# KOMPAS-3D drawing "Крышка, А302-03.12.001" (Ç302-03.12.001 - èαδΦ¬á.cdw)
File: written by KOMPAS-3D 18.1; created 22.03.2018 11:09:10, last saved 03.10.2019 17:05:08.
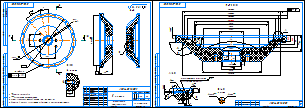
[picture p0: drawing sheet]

Sheets 1-2: A3, landscape

Document properties: Автор: Милов; Организация: Милов; Полное имя файла: D:\Мембранные насосы\Мембранный электропривод\А302-00.00.000 - ASTRA-302 (МЭ200)\Чертежи Полипропилен\А302-03.12.001 - Крышка.cdw; Масса: 2.71786; Параметр неуказанной шероховатости: Ra 3,2; Форматы листов документа: 2xA3

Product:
- Part/product: Крышка  | designation А302-03.12.001
    Материал: Поливинилхлорид (density 1350 kg/m3)
    Масса: 2.71786
    Раздел спецификации: Детали
    Форматы листов документа: 2xA3
    Примечание: @100~)2xA3
    source file: А302-03.12.001 - Крышка.cdw
- Part/product: Крышка  | designation А302-01.12.001
    Материал: Поливинилхлорид (density 1350 kg/m3)
    Масса: 2.45398
    Раздел спецификации: Детали
    Форматы листов документа: 2xA3
    Примечание: @100~)2xA3
    source file: ..\3Д ПВХ\А302-01.12.001 - Крышка.cdw
- Part/product: Крышка  | designation А302-02.12.001
    Материал: Поливинилхлорид (density 1350 kg/m3)
    Масса: 2.64473
    Раздел спецификации: Детали
    Форматы листов документа: 2xA3
    Примечание: @100~)2xA3
    source file: ..\3Д ПВХ\А302-02.00.000 - ASTRA-302 (МЭ200)\А302-02.12.001 - Крышка.cdw, ..\Чертежи ПВХ\А302-02.12.001 - Крышка.cdw

Title block, sheet 1: Наименование: Крышка; designation: А302-03.12.001; Материал: Полипропилен / Стержень  300; Масса: 2,72; scale: 1:2; sheet number: 1; Количество листов документа: 2; organisation: АО «Астерион»; Форматы листов документа: A3; stored path: Z:\Мембранные насосы\Мембранный электропривод\А302-00.00.000 - ASTRA-302 (МЭ200)\Чертежи\А302-00.12.001 - Крышка.cdw; Разработал: Лифлянд; Проверил: Борисенко; Т. контр.: Лучихин; Утвердил: Григорьева
Title block, sheet 2: sheet number: 2

Views: Вид 1, Вид:4, Проекционный вид 2, Местный разрез 1, Разрез А-А, Выносной элемент 4, Выносной элемент 5, Выносной элемент 7, Разрез Г-Г, Выносной элемент А, Выносной элемент, Выносной элемент Б, Разрез Д-Д, Выносной элемент В, Вид:1, Вид:2, Вид:3
Referenced files in Z:\Мембранные насосы\Мембранный электропривод\А302-00.00.000 - ASTRA-302 (МЭ200)\3Д\: А302-00.12.001 - Крышка.m3d
Referenced files in D:\Мембранные насосы\Мембранный электропривод\А302-00.00.000 - ASTRA-302 (МЭ200)\3Д ПВХ\: А302-01.12.001 - Крышка.m3d
Referenced files in \\192.168.87.28\Konstructor_doc\Мембранные насосы\Мембранный электропривод\А302-00.00.000 - ASTRA-302 (МЭ200)\3Д ПВХ\: А302-01.12.001 - Крышка.m3d
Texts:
  Зона контакта с мембраной
  поверхность глянцевая
  Ra 3,2
  Ra 3,2 ( )
Dimensions and other numbers on the sheet: 300; 287; 12 отв.; 6,5; 10; 6 отв.; 88; 70; 2; 280; 72; 270±0,4; 16,9; 24,5; 244±0,2; 206; 202; 155,4; 6; 0,5; 258±0,3; 0,1; 33; 44; 64,6; 42,6; 163; 18; 10,5; 49,5; 19; 135; 1; 3; 56; 12,5; 12; 0,8; 2 места; 6 мест; 20; 15; 1:2; 2,72; 18.09.2019; 03.10.2019

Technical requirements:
  *Размеры для справок.
  ** Обеспечить инструментом.
  Общие допуски ГОСТ 30893.2-mK (H14, h14,  t2/2).
  Размеры в скобках обработать совместно с сопрягаемой деталью.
